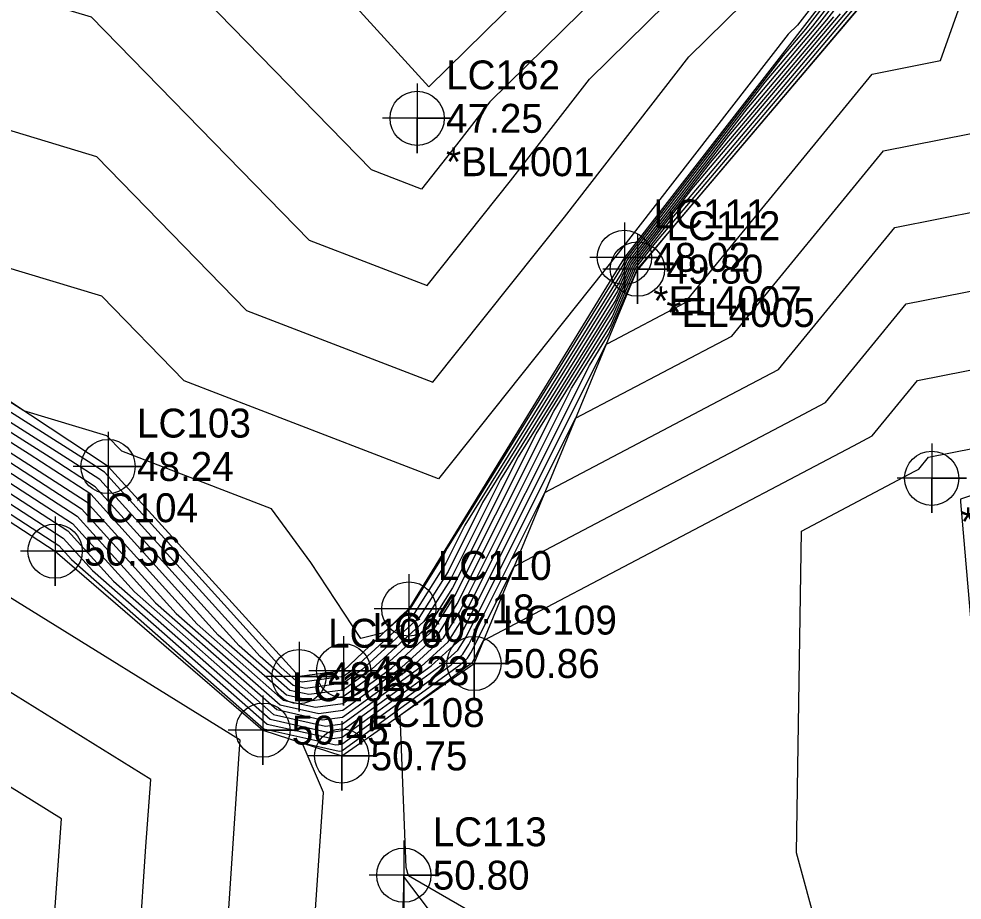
# Model space of a CAD drawing. Extents: x 2188792 to 2191981, y 386090 to 389710.
# Drawn here: x 2189959 to 2190040.5, y 387535.2 to 387611.4 of the extents above; entities that cross this region are included whole.
import ezdxf

# ---------------------------------------------------------------- set-up
doc = ezdxf.new("R2010")
doc.units = 0
for name, color, linetype in [('DTM Contours Major', 7, 'Continuous'), ('DTM Contours Minor', 7, 'Continuous'), ('Exist DTM Breakline', 7, 'Continuous'), ('Exist DTM Breakline Cogo Comment', 7, 'Continuous'), ('Exist DTM Breakline Cogo Elevation', 7, 'Continuous'), ('Exist DTM Breakline Cogo Number', 7, 'Continuous'), ('Exist DTM Breakline Cogo Point CELL', 7, 'Continuous'), ('Exist DTM Breakline Underwater', 7, 'Continuous'), ('Exist DTM Breakline Underwater Cogo Comment', 7, 'Continuous'), ('Exist DTM Breakline Underwater Cogo Elevation', 7, 'Continuous'), ('Exist DTM Breakline Underwater Cogo Number', 7, 'Continuous'), ('Exist DTM Breakline Underwater Cogo Point CELL', 7, 'Continuous'), ('Exist DTM Regular Point Underwater CELL', 7, 'Continuous'), ('Exist DTM Regular Point Underwater Cogo Comment', 7, 'Continuous'), ('Exist DTM Regular Point Underwater Cogo Elevation', 7, 'Continuous'), ('Exist DTM Regular Point Underwater Cogo Number', 7, 'Continuous')]:
    doc.layers.add(name, color=color, linetype=linetype)

msp = doc.modelspace()

# ---------------------------------------------------------------- linework, layer by layer
at = {"layer": 'DTM Contours Major'}
for points in [[(2189979.143, 387677.851), (2189984.677, 387683.753), (2189992.617, 387687.981), (2190022.386, 387704.238), (2190022.134, 387706.157), (2190018.692, 387711.884), (2190024.663, 387708.095), (2190028.689, 387705.544), (2190032.058, 387703.311), (2190053.475, 387688.732), (2190053.972, 387688.406), (2190055.021, 387687.68), (2190053.937, 387684.644), (2190054.747, 387651.06), (2190044.441, 387634.235), (2190026.282, 387610.832), (2190025.484, 387610.047), (2190010.801, 387591.125), (2189995.266, 387571.631), (2189973.274, 387580.098), (2189966.148, 387587.407), (2189944.825, 387593.838)], [(2190028.053, 387532.529), (2190026.213, 387539.316), (2190026.623, 387567.116), (2190036.437, 387572.281), (2190036.783, 387572.463), (2190037.624, 387573.49), (2190071.228, 387580.123), (2190040.365, 387569.873), (2190040.385, 387569.638), (2190043.386, 387534.826), (2190057.87, 387555.38), (2190057.878, 387555.392), (2190058.608, 387556.427), (2190060.211, 387558.646), (2190075.692, 387581.242), (2190075.723, 387581.285), (2190076.015, 387581.713), (2190081.298, 387607.701), (2190080.405, 387617.391)], [(2189950.861, 387575.147), (2189963.225, 387567.139), (2189967.166, 387562.783), (2189980.719, 387550.845), (2189985.8, 387549.716), (2189986.946, 387549.87), (2189994.633, 387555.459), (2189996.519, 387557.184), (2189997.475, 387558.702), (2190009.762, 387583.253), (2190009.909, 387583.33), (2190016.564, 387586.832), (2190032.751, 387606.61), (2190038.644, 387607.773), (2190040.515, 387613.076)], [(2190029.401, 387611.552), (2190018.745, 387598.966), (2190011.951, 387590.209), (2190010.579, 387587.106), (2190002.151, 387573.541), (2189996.485, 387562.22), (2189994.42, 387558.94), (2189990.348, 387555.217), (2189987.011, 387552.791), (2189984.34, 387552.432), (2189982.125, 387552.924), (2189976.216, 387558.129), (2189965.202, 387570.301), (2189959.878, 387573.749), (2189943.268, 387584.286)], [(2189956.665, 387461.26), (2189960.354, 387469.136), (2189960.736, 387469.517), (2189964.05, 387469.936), (2189971.173, 387472.29), (2189973.658, 387482.085), (2189974.62, 387510.207), (2189961.043, 387518.678), (2189961.921, 387531.826), (2189962.671, 387542.238), (2189947.626, 387551.564)]]:
    msp.add_lwpolyline(points, dxfattribs=at)
at = {"layer": 'DTM Contours Minor'}
for points in [[(2189984.526, 387532.738), (2189985.313, 387544.525), (2189983.467, 387548.799), (2189986.676, 387548.086), (2189986.906, 387548.117), (2189997.205, 387555.605), (2189997.778, 387556.129), (2189998.069, 387556.592), (2190001.808, 387564.061), (2190025.826, 387576.7), (2190028.696, 387578.211), (2190035.675, 387586.738), (2190061.031, 387591.743), (2190069.081, 387614.559), (2190069.859, 387615.525), (2190068.063, 387633.741), (2190066.198, 387657.229), (2190065.615, 387658.574), (2190075.795, 387674.685), (2190075.782, 387675.298), (2190088.219, 387667.856), (2190097.569, 387698.156), (2190082.81, 387743.315), (2190129.137, 387764.957)], [(2190027.247, 387517.328), (2189992.67, 387537.316), (2189992.479, 387538.021), (2189991.936, 387551.2), (2189998.062, 387555.653), (2189998.198, 387555.778), (2189998.267, 387555.888), (2189999.156, 387557.664), (2190031.132, 387574.491), (2190032.739, 387575.337), (2190036.649, 387580.114), (2190068.493, 387586.4), (2190073.131, 387599.545), (2190075.577, 387611.576), (2190075.181, 387615.87), (2190075.838, 387624.97), (2190073.15, 387658.812), (2190070.209, 387665.603), (2190075.916, 387674.635), (2190075.909, 387674.98), (2190089.633, 387666.767), (2190099.951, 387700.204), (2190086.743, 387740.615), (2190128.2, 387759.982)], [(2189951.602, 387603.735), (2189965.697, 387599.484), (2189978.671, 387586.177), (2189994.77, 387579.978), (2190006.142, 387594.249), (2190016.891, 387608.101), (2190024.734, 387615.811), (2190040.843, 387636.572), (2190049.986, 387651.498), (2190049.178, 387684.995), (2190028.436, 387704.924), (2190028.414, 387704.945)], [(2189943.41, 387635.494), (2189960.087, 387622.643), (2189958.379, 387613.632), (2189965.246, 387611.561), (2189984.068, 387592.256), (2189994.274, 387588.326), (2190001.484, 387597.373), (2190008.298, 387606.155), (2190023.185, 387620.79), (2190037.245, 387638.909), (2190045.225, 387651.937), (2190044.52, 387681.172), (2190026.416, 387698.565), (2190024.64, 387700.3)], [(2189965.072, 387623.375), (2189979.676, 387668.152), (2189984.921, 387674.147), (2189988.672, 387678.147), (2189994.052, 387681.011), (2190020.867, 387695.655), (2190024.397, 387692.206), (2190039.861, 387677.348), (2190040.463, 387652.375), (2190033.647, 387641.247), (2190021.637, 387625.768), (2189999.705, 387604.208), (2189996.825, 387600.497), (2189993.778, 387596.673), (2189989.465, 387598.334), (2189966.646, 387621.739), (2189965.222, 387623.304), (2189965.072, 387623.375)], [(2189970.145, 387630.191), (2189982.434, 387667.868), (2189986.848, 387672.913), (2189990.003, 387676.278), (2189994.53, 387678.688), (2190017.093, 387691.01), (2190022.377, 387685.847), (2190035.203, 387673.525), (2190035.702, 387652.813), (2190030.049, 387643.584), (2190020.089, 387630.747), (2189994.416, 387605.51), (2189973.301, 387628.703), (2189970.145, 387630.191)], [(2190043.563, 387631.862), (2190026.992, 387610.501), (2190025.058, 387608.217), (2190011.444, 387590.667), (2190011.195, 387590.105), (2189996, 387565.648), (2189995.693, 387565.035), (2189992.74, 387560.346), (2189990.507, 387558.303), (2189988.535, 387557.816), (2189984.231, 387564.391), (2189980.829, 387569.033), (2189967.877, 387574.02), (2189966.599, 387575.33), (2189959.426, 387577.494), (2189941.853, 387588.642)], [(2190042.117, 387629.485), (2190027.594, 387610.764), (2190023.48, 387605.904), (2190011.571, 387590.553), (2190011.041, 387589.355), (2189997.538, 387567.621), (2189995.891, 387564.331), (2189993.16, 387559.995), (2189987.777, 387555.071), (2189987.051, 387554.543), (2189983.464, 387554.061), (2189982.968, 387554.172), (2189981.645, 387555.336), (2189966.389, 387572.198), (2189965.289, 387572.91), (2189942.207, 387587.553)], [(2190040.672, 387627.108), (2190028.197, 387611.026), (2190021.901, 387603.592), (2190011.698, 387590.438), (2190010.887, 387588.605), (2189999.075, 387569.594), (2189996.089, 387563.627), (2189993.58, 387559.643), (2189988.634, 387555.119), (2189987.038, 387553.959), (2189983.756, 387553.518), (2189982.687, 387553.756), (2189979.836, 387556.267), (2189965.993, 387571.565), (2189963.485, 387573.19), (2189942.561, 387586.464)], [(2190039.226, 387624.731), (2190028.799, 387611.289), (2190020.323, 387601.279), (2190011.824, 387590.323), (2190010.733, 387587.855), (2190000.613, 387571.568), (2189996.287, 387562.924), (2189994, 387559.292), (2189989.491, 387555.168), (2189987.025, 387553.375), (2189984.048, 387552.975), (2189982.406, 387553.34), (2189978.026, 387557.198), (2189965.598, 387570.933), (2189961.682, 387573.469), (2189942.914, 387585.375)], [(2189947.255, 387575.706), (2189962.434, 387565.874), (2189963.546, 387564.645), (2189980.157, 387550.013), (2189986.384, 387548.629), (2189986.919, 387548.701), (2189996.347, 387555.556), (2189997.358, 387556.481), (2189997.871, 387557.295), (2190004.459, 387570.458), (2190020.52, 387578.91), (2190024.652, 387581.084), (2190034.7, 387593.362), (2190053.569, 387597.086), (2190059.559, 387614.065)], [(2189949.058, 387575.426), (2189962.83, 387566.507), (2189965.356, 387563.714), (2189980.438, 387550.429), (2189986.092, 387549.173), (2189986.932, 387549.285), (2189995.49, 387555.508), (2189996.939, 387556.832), (2189997.673, 387557.999), (2190007.111, 387576.856), (2190015.215, 387581.12), (2190020.608, 387583.958), (2190033.725, 387599.986), (2190046.106, 387602.43), (2190050.037, 387613.57)], [(2189952.665, 387574.867), (2189963.621, 387567.771), (2189968.976, 387561.852), (2189981, 387551.26), (2189985.508, 387550.259), (2189986.959, 387550.454), (2189993.776, 387555.411), (2189996.099, 387557.535), (2189997.277, 387559.406), (2190008.302, 387581.434), (2190009.962, 387584.107), (2190012.414, 387589.65), (2190012.521, 387589.706), (2190015.342, 387593.153), (2190031.81, 387612.603)], [(2189954.468, 387574.588), (2189964.016, 387568.404), (2189970.786, 387560.922), (2189981.281, 387551.676), (2189985.216, 387550.802), (2189986.972, 387551.038), (2189992.919, 387555.362), (2189995.679, 387557.886), (2189997.079, 387560.109), (2190006.764, 387579.461), (2190010.116, 387584.856), (2190012.331, 387589.865), (2190014.009, 387592.028), (2190031.208, 387612.34)], [(2189956.272, 387574.308), (2189964.411, 387569.036), (2189972.596, 387559.991), (2189981.562, 387552.092), (2189984.924, 387551.345), (2189986.985, 387551.622), (2189992.062, 387555.314), (2189995.259, 387558.238), (2189996.881, 387560.813), (2190005.226, 387577.487), (2190010.271, 387585.606), (2190012.205, 387589.98), (2190015.588, 387594.341), (2190030.606, 387612.078)], [(2189958.075, 387574.028), (2189964.807, 387569.668), (2189974.406, 387559.06), (2189981.844, 387552.508), (2189984.632, 387551.889), (2189986.998, 387552.206), (2189991.205, 387555.265), (2189994.839, 387558.589), (2189996.683, 387561.517), (2190003.689, 387575.514), (2190010.425, 387586.356), (2190012.078, 387590.094), (2190017.166, 387596.653), (2190030.003, 387611.815)], [(2189954.903, 387454.862), (2189959.081, 387458.988), (2189961.556, 387464.272), (2189963.77, 387466.483), (2189974.639, 387467.856), (2189976.863, 387467.842), (2189979.229, 387470.893), (2189982.035, 387481.952), (2189983.467, 387523.828), (2189976.698, 387528.051), (2189978.02, 387547.851), (2189978.106, 387549.034), (2189958.031, 387561.478)], [(2189957.873, 387460.124), (2189960.955, 387466.704), (2189962.253, 387468), (2189973.526, 387469.424), (2189974.754, 387469.829), (2189977.847, 387482.019), (2189979.043, 387517.017), (2189968.871, 387523.365), (2189969.971, 387539.838), (2189970.388, 387545.636), (2189952.829, 387556.521)], [(2189990.412, 387481.82), (2189992.305, 387537.181), (2190016.966, 387504.647)]]:
    msp.add_lwpolyline(points, dxfattribs=at)
at = {"layer": 'Exist DTM Breakline'}
msp.add_lwpolyline([(2189920.868, 387592.295), (2189962.123, 387565.377), (2189980.085, 387549.906), (2189986.896, 387547.677), (2189998.329, 387555.668), (2190012.456, 387589.752), (2190048.075, 387631.731), (2190076.07, 387674.573), (2190074.562, 387678.377), (2190070.092, 387679.666), (2190029.766, 387708.101), (2190010.729, 387719.436), (2190038.07, 387742.576)], dxfattribs=at)
at = {"layer": 'Exist DTM Breakline Cogo Point CELL'}
for points in [[(2190012.456, 387592.752), (2190012.456, 387586.752), (2190012.456, 387589.752), (2190015.456, 387589.752), (2190009.456, 387589.752)], [(2189962.123, 387568.377), (2189962.123, 387562.377), (2189962.123, 387565.377), (2189965.123, 387565.377), (2189959.123, 387565.377)], [(2189998.329, 387558.668), (2189998.329, 387552.668), (2189998.329, 387555.668), (2190001.329, 387555.668), (2189995.329, 387555.668)], [(2189980.085, 387552.906), (2189980.085, 387546.906), (2189980.085, 387549.906), (2189983.085, 387549.906), (2189977.085, 387549.906)], [(2189986.896, 387550.677), (2189986.896, 387544.677), (2189986.896, 387547.677), (2189989.896, 387547.677), (2189983.896, 387547.677)]]:
    msp.add_lwpolyline(points, dxfattribs=at)
for centre in [(2190012.456, 387589.752), (2189962.123, 387565.377), (2189998.329, 387555.668), (2189980.085, 387549.906), (2189986.896, 387547.677)]:
    msp.add_circle(centre, 2.344, dxfattribs=at)
at = {"layer": 'Exist DTM Breakline Underwater'}
msp.add_lwpolyline([(2190044.846, 387633.972), (2190011.332, 387590.769), (2189992.696, 387560.383), (2189987.062, 387555.03), (2189983.211, 387554.531), (2189966.698, 387572.692), (2189926.493, 387599.241)], dxfattribs=at)
at = {"layer": 'Exist DTM Breakline Underwater Cogo Point CELL'}
for points in [[(2190011.332, 387593.769), (2190011.332, 387587.769), (2190011.332, 387590.769), (2190014.332, 387590.769), (2190008.332, 387590.769)], [(2189966.698, 387575.692), (2189966.698, 387569.692), (2189966.698, 387572.692), (2189969.698, 387572.692), (2189963.698, 387572.692)], [(2189992.696, 387563.383), (2189992.696, 387557.383), (2189992.696, 387560.383), (2189995.696, 387560.383), (2189989.696, 387560.383)], [(2189987.062, 387558.03), (2189987.062, 387552.03), (2189987.062, 387555.03), (2189990.062, 387555.03), (2189984.062, 387555.03)], [(2189983.211, 387557.531), (2189983.211, 387551.531), (2189983.211, 387554.531), (2189986.211, 387554.531), (2189980.211, 387554.531)]]:
    msp.add_lwpolyline(points, dxfattribs=at)
for centre in [(2190011.332, 387590.769), (2189966.698, 387572.692), (2189992.696, 387560.383), (2189987.062, 387555.03), (2189983.211, 387554.531)]:
    msp.add_circle(centre, 2.344, dxfattribs=at)
at = {"layer": 'Exist DTM Regular Point Underwater CELL'}
for points in [[(2189993.415, 387605.784), (2189993.415, 387599.784), (2189993.415, 387602.784), (2189996.415, 387602.784), (2189990.415, 387602.784)], [(2190037.891, 387574.675), (2190037.891, 387568.675), (2190037.891, 387571.675), (2190040.891, 387571.675), (2190034.891, 387571.675)], [(2189992.263, 387540.371), (2189992.263, 387534.371), (2189992.263, 387537.371), (2189995.263, 387537.371), (2189989.263, 387537.371)]]:
    msp.add_lwpolyline(points, dxfattribs=at)
for centre in [(2189993.415, 387602.784), (2190037.891, 387571.675), (2189992.263, 387537.371)]:
    msp.add_circle(centre, 2.344, dxfattribs=at)

# ---------------------------------------------------------------- texts
at = {"layer": 'Exist DTM Breakline Cogo Comment'}
msp.add_text('*EL4005', height=2.5, dxfattribs=at).set_placement((2190014.956, 387584.752))
at = {"layer": 'Exist DTM Breakline Cogo Elevation'}
for s, p in [('49.80', (2190014.956, 387588.502)), ('50.56', (2189964.623, 387564.127)), ('50.86', (2190000.829, 387554.418)), ('50.45', (2189982.585, 387548.656)), ('50.75', (2189989.396, 387546.427))]:
    msp.add_text(s, height=2.5, dxfattribs=at).set_placement(p)
at = {"layer": 'Exist DTM Breakline Cogo Number'}
for s, p in [('LC112', (2190014.956, 387592.252)), ('LC104', (2189964.623, 387567.877)), ('LC109', (2190000.829, 387558.168)), ('LC105', (2189982.585, 387552.406)), ('LC108', (2189989.396, 387550.177))]:
    msp.add_text(s, height=2.5, dxfattribs=at).set_placement(p)
at = {"layer": 'Exist DTM Breakline Underwater Cogo Comment'}
msp.add_text('*EL4007', height=2.5, dxfattribs=at).set_placement((2190013.832, 387585.769))
at = {"layer": 'Exist DTM Breakline Underwater Cogo Elevation'}
for s, p in [('48.02', (2190013.832, 387589.519)), ('48.24', (2189969.198, 387571.442)), ('48.18', (2189995.196, 387559.133)), ('48.23', (2189989.562, 387553.78)), ('48.23', (2189985.711, 387553.281))]:
    msp.add_text(s, height=2.5, dxfattribs=at).set_placement(p)
at = {"layer": 'Exist DTM Breakline Underwater Cogo Number'}
for s, p in [('LC111', (2190013.832, 387593.269)), ('LC103', (2189969.198, 387575.192)), ('LC110', (2189995.196, 387562.883)), ('LC106', (2189985.711, 387557.031)), ('LC107', (2189989.562, 387557.53))]:
    msp.add_text(s, height=2.5, dxfattribs=at).set_placement(p)
at = {"layer": 'Exist DTM Regular Point Underwater Cogo Comment'}
for s, p in [('*BL4001', (2189995.915, 387597.784)), ('*EL4001', (2190040.391, 387566.675))]:
    msp.add_text(s, height=2.5, dxfattribs=at).set_placement(p)
at = {"layer": 'Exist DTM Regular Point Underwater Cogo Elevation'}
for s, p in [('47.25', (2189995.915, 387601.534)), ('50.80', (2189994.763, 387536.121))]:
    msp.add_text(s, height=2.5, dxfattribs=at).set_placement(p)
at = {"layer": 'Exist DTM Regular Point Underwater Cogo Number'}
for s, p in [('LC162', (2189995.915, 387605.284)), ('LC113', (2189994.763, 387539.871))]:
    msp.add_text(s, height=2.5, dxfattribs=at).set_placement(p)

doc.saveas('drawing.dxf')
